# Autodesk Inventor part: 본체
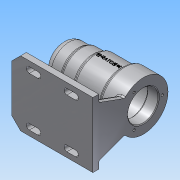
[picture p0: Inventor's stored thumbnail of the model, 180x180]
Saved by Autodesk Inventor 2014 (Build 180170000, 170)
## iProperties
Created: 2017-09
Part Number: 본체
Material: 알루미늄 6061
Document SubType Name: Modeling
Designer: NET
Density: 2.71 g/cm^3
Appearance: 알루미늄 - 평지
Mass: 699.003 g
Surface Area: 709.206 cm^2
Volume: 257.935 cm^3
Author: NET
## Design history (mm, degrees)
sketch "스케치1"
  geometry: L1 (0, 0)-(112, 0); L2 (0, 0)-(0, 25); L3 (0, 25)-(25, 25); L4 (25, 25)-(25, 27); L5 (25, 27)-(45, 27); L6 (45, 27)-(45, 30); L7 (45, 30)-(84, 30); L8 (84, 30)-(84, 34); L9 (84, 34)-(112, 34); L10 (112, 34)-(112, 0)
  constraints: 20 end point, 6 parallel, 3 perpendicular, 1 horizontal
  dimensions: "d0" = 50 diameter of L3 L1; "d1" = 54 diameter of L5 L1; "d2" = 60 diameter of L7 L1; "d3" = 68 diameter of L9 L1; "d4" = 25 distance of L2.end L3.end; "d5" = 45 distance from line of L2 L6.end; "d6" = 84 distance between parallel lines of L2 L8; "d7" = 112 distance from line of L2 L9.end
revolve "회전1" sketch "스케치1" stored, may be unused: angle "d8" = 90 deg
fillet "모깎기1" dims "d9" = 9
fillet "모깎기2" dims "d10" = 3
sketch "스케치2"
  geometry: L1 (81, -30)-(47.196, -30) reference; L2 (42, -27)-(26.644, -27) reference; L3 (22.172, -25)-(9, -25) reference; L4 (0, -16)-(0, 16) reference; L5 (9, 25)-(22.172, 25) reference; L6 (26.644, 27)-(42, 27) reference; L7 (47.196, 30)-(81, 30) reference; L8 (86.657, 34)-(112, 34) reference; L9 (112, 34)-(112, -34) reference; L10 (112, -34)-(86.657, -34) reference; L11 (6, 0)-(112, 0); L12 (112, -34)-(112, 34) reference; L13 (6, 0)-(6, 10.5); L14 (6, 10.5)-(9, 10.5); L15 (9, 10.5)-(9, 16); L16 (9, 16)-(13, 16); L17 (13, 16)-(13, 17.5); L18 (13, 17.5)-(31, 17.5); L19 (31, 17.5)-(31, 21); L20 (31, 21)-(43, 21); L21 (43, 21)-(43, 24); L22 (43, 24)-(97, 24); L23 (97, 24)-(97, 21); L24 (97, 21)-(112, 21); L25 (112, 21)-(112, 0); A1 r 3 centre (86.657, -31) between (83.828, -32) and (86.657, -34) reference; A2 r 3 centre (81, -33) between (83.828, -32) and (81, -30) reference; A3 r 3 centre (47.196, -27) between (44.598, -28.5) and (47.196, -30) reference; A4 r 3 centre (42, -30) between (44.598, -28.5) and (42, -27) reference; A5 r 3 centre (26.644, -24) between (24.408, -26) and (26.644, -27) reference; A6 r 3 centre (22.172, -28) between (24.408, -26) and (22.172, -25) reference; A7 r 9 centre (9, -16) between (0, -16) and (9, -25) reference; A8 r 9 centre (9, 16) between (9, 25) and (0, 16) reference; A9 r 3 centre (22.172, 28) between (22.172, 25) and (24.408, 26) reference; A10 r 3 centre (26.644, 24) between (26.644, 27) and (24.408, 26) reference; A11 r 3 centre (42, 30) between (42, 27) and (44.598, 28.5) reference; A12 r 3 centre (47.196, 27) between (47.196, 30) and (44.598, 28.5) reference; A13 r 3 centre (81, 33) between (81, 30) and (83.828, 32) reference; A14 r 3 centre (86.657, 31) between (86.657, 34) and (83.828, 32) reference; 1 further point
  constraints: 28 end point, 6 parallel, 6 perpendicular, 1 midpoint, 1 point on line, 1 vertical
  dimensions: "d11" = 3 distance of L13.end L14.end; "d12" = 4 distance of L15.end L16.end; "d13" = 18 distance of L17.end L18.end; "d14" = 12 distance of L19.end L20.end; "d15" = 54 distance of L21.end L22.end; "d16" = 15 distance of L23.end L24.end; "d17" = 21 diameter of L14 L11; "d18" = 32 diameter of L16 L11; "d19" = 35 diameter of L18 L11; "d20" = 42 diameter of L20 L11; "d21" = 48 diameter of L22 L11; "d22" = 42 diameter of L24 L11
revolve "회전2" sketch "스케치2" stored, may be unused: angle "d23" = 90 deg
chamfer "모따기1" distance "d24" = 1; stored, may be unused: second distance "d25" = 2, angle "d26" = 45 deg
fillet "모깎기3" dims "d27" = 3
fillet "모깎기4" dims "d28" = 0.3
fillet "모깎기5" dims "d29" = 3
sketch "스케치3" dims "d30" = 52
  geometry: C1 r 34 at (0, 0) reference; C2 r 22 at (0, 0) reference; 2 further points
  constraints: 2 vertical alignment, 1 coincident, 2 other
hole "구멍1" sketch "스케치3" at (0, 26) diameter "d31" = 3.242; stored, may be unused: countersink angle "d35" = 90 deg, drill point angle "d37" = 118 deg; dims "d32" = 8, "d33" = 4, "d34" = 2, "d36" = 11
node "작업 평면1"
sketch "스케치4"
  geometry: L1 (0, 16)-(0, -16) reference; L2 (-112, 34)-(-112, -34) reference; L3 (-86.657, 34)-(-112, 34) reference; L4 (-86.657, -34)-(-112, -34) reference; L5 (-112, 0)-(0, 0); L6 (-112, 45)-(0, 45); L7 (0, 45)-(0, -45); L8 (0, -45)-(-112, -45); L9 (-112, -45)-(-112, 45); L10 (-112, 45)-(0, -45); L11 (0, 45)-(-112, -45); 3 further points
  constraints: 14 end point, 5 midpoint, 3 parallel, 1 coincident, 1 horizontal, 1 horizontal alignment, 1 perpendicular
  dimensions: "d43" = 90 distance of L8.end L6.start; "d44" = 112 distance of L6.start L6.end
extrude "돌출1" join sketch "스케치4" distance "d45" = 8; taper "d46" = 0 deg
sketch "스케치5" dims "d43" = 90
  geometry: L1 (0, -45)-(112, -45) reference; L2 (0, 45)-(0, -45) reference; L3 (24, 34)-(36, 34); L4 (24, 30)-(36, 30); L5 (36, 38)-(24, 38); L6 (76, 34)-(88, 34); L7 (76, 30)-(88, 30); L8 (88, 38)-(76, 38); A1 r 4 centre (24, 34) between (24, 38) and (24, 30); A2 r 4 centre (36, 34) between (36, 30) and (36, 38); A3 r 4 centre (76, 34) between (76, 38) and (76, 30); A4 r 4 centre (88, 34) between (88, 30) and (88, 38); 3 further points
  constraints: 16 end point, 8 point on circle, 8 tangent, 4 centre point, 4 parallel, 2 midpoint, 1 horizontal alignment
  dimensions: "d47" = 34 vertical distance of point (0, 0) L3.start; "d48" = 4 radius of A1; "d49" = 12 distance of L3.start L3.end; "d50" = 40 distance of L6.start L3.end; "d51" = 24 distance from line of L2 L3.start; "d52" = 12 distance of L6.start L6.end; "d53" = 4 radius of A3
extrude "돌출2" cut sketch "스케치5" distance "d54" = 8; taper "d55" = 0 deg
chamfer "모따기2" distance "d56" = 12; stored, may be unused: second distance "d57" = 2, angle "d58" = 45 deg
sketch "스케치6"
  geometry: L1 (-45, -62)-(45, -62) reference; L2 (-63, -70)-(63, -70) reference; L3 (-45, -70)-(-45, -62) reference; L4 (45, -70)-(45, -62) reference; L5 (35, -62)-(21.9, -26.008); L6 (-35, -62)-(-21.9, -26.008); L7 (-35, -62)-(35, -62); L8 (30, -62)-(38, -62) reference; A1 r 34 centre (0, 0) between (21.9, -26.008) and (-21.9, -26.008) reference; 1 further point
  constraints: 6 end point, 2 point on circle, 2 point on line, 1 collinear, 2 other
  dimensions: "d59" = 10 distance from line of L3 L6.start; "d60" = 10 distance from line of L4 L5.start; "d61" = 70 deg angle of L1 L6; "d62" = 70 deg angle of L1 L5
extrude "돌출3" join sketch "스케치6" distance "d63" = 8; taper "d64" = 0 deg
sketch "스케치7"
  geometry: L1 (112, 22)-(111, 21) reference; L2 (111, 21)-(97, 21) reference; L3 (94, 24)-(46, 24) reference; L4 (43, 21)-(31.3, 21) reference; L5 (31, 20.7)-(31, 17.5) reference; L6 (31, 17.5)-(13.3, 17.5) reference; L7 (13, 17.2)-(13, 16) reference; L8 (13, 16)-(9.3, 16) reference; L9 (9, 15.7)-(9, 10.5) reference; L10 (6, 7.5)-(6, -7.5) reference; L11 (9, -10.5)-(9, -15.7) reference; L12 (9.3, -16)-(13, -16) reference; L13 (13, -16)-(13, -17.2) reference; L14 (13.3, -17.5)-(31, -17.5) reference; L15 (31, -17.5)-(31, -20.7) reference; L16 (31.3, -21)-(43, -21) reference; L17 (46, -24)-(94, -24) reference; L18 (97, -21)-(111, -21) reference; L19 (111, -21)-(112, -22) reference; L20 (112, -22)-(112, -70) reference; L21 (112, -70)-(0, -70) reference; L22 (0, -70)-(0, -62) reference; L23 (0, -62)-(104, -62) reference; L24 (104, -62)-(104, -34) reference; L25 (104, -34)-(86.657, -34) reference; L26 (81, -30)-(47.196, -30) reference; L27 (42, -27)-(26.644, -27) reference; L28 (22.172, -25)-(9, -25) reference; L29 (0, -16)-(0, 16) reference; L30 (9, 25)-(22.172, 25) reference; L31 (26.644, 27)-(42, 27) reference; L32 (47.196, 30)-(81, 30) reference; L33 (86.657, 34)-(112, 34) reference; L34 (112, 34)-(112, 27.621) reference; L35 (112, 27.621)-(101, 27.621) reference; L36 (101, 27.621)-(100.026, 26) reference; L37 (100.026, 26)-(101, 24.379) reference; L38 (101, 24.379)-(112, 24.379) reference; L39 (112, 24.379)-(112, 22) reference; L40 (112, -62)-(12, -62) reference; L41 (22, -62)-(31.378, -27); L42 (22, -62)-(104, -62); L43 (104, -62)-(112, -62) reference; L44 (104, -62)-(104, -59.048); L45 (31.378, -27)-(33.181, -24); L46 (33.181, -24)-(53.836, -28); L47 (53.836, -28)-(73.946, -28); L48 (73.946, -28)-(94, -28.5); L49 (94, -28.5)-(104, -30.437); L50 (104, -26.008)-(104, -62) reference; L51 (104, -30.437)-(104, -34); A1 r 3 centre (94, 21) between (97, 21) and (94, 24) reference; A2 r 3 centre (46, 21) between (46, 24) and (43, 21) reference; A3 r 0.3 centre (31.3, 20.7) between (31.3, 21) and (31, 20.7) reference; A4 r 0.3 centre (13.3, 17.2) between (13.3, 17.5) and (13, 17.2) reference; A5 r 0.3 centre (9.3, 15.7) between (9.3, 16) and (9, 15.7) reference; A6 r 3 centre (9, 7.5) between (9, 10.5) and (6, 7.5) reference; A7 r 3 centre (9, -7.5) between (6, -7.5) and (9, -10.5) reference; A8 r 0.3 centre (9.3, -15.7) between (9, -15.7) and (9.3, -16) reference; A9 r 0.3 centre (13.3, -17.2) between (13, -17.2) and (13.3, -17.5) reference; A10 r 0.3 centre (31.3, -20.7) between (31, -20.7) and (31.3, -21) reference; A11 r 3 centre (46, -21) between (43, -21) and (46, -24) reference; A12 r 3 centre (94, -21) between (94, -24) and (97, -21) reference; A13 r 3 centre (86.657, -31) between (83.828, -32) and (86.657, -34) reference; A14 r 3 centre (81, -33) between (83.828, -32) and (81, -30) reference; A15 r 3 centre (47.196, -27) between (44.598, -28.5) and (47.196, -30) reference; A16 r 3 centre (42, -30) between (44.598, -28.5) and (42, -27) reference; A17 r 3 centre (26.644, -24) between (24.408, -26) and (26.644, -27) reference; A18 r 3 centre (22.172, -28) between (24.408, -26) and (22.172, -25) reference; A19 r 9 centre (9, -16) between (0, -16) and (9, -25) reference; A20 r 9 centre (9, 16) between (9, 25) and (0, 16) reference; A21 r 3 centre (22.172, 28) between (22.172, 25) and (24.408, 26) reference; A22 r 3 centre (26.644, 24) between (26.644, 27) and (24.408, 26) reference; A23 r 3 centre (42, 30) between (42, 27) and (44.598, 28.5) reference; A24 r 3 centre (47.196, 27) between (47.196, 30) and (44.598, 28.5) reference; A25 r 3 centre (81, 33) between (81, 30) and (83.828, 32) reference; A26 r 3 centre (86.657, 31) between (86.657, 34) and (83.828, 32) reference; 1 further point
  constraints: 18 end point, 4 point on line, 2 collinear, 2 parallel, 1 perpendicular
  dimensions: "d65" = 105 deg angle of L23 L41; "d66" = 22 distance from line of L22 L41.start
extrude "돌출4" join sketch "스케치7" stored distance "d67" = 8; taper "d68" = 0 deg
node "작업 평면2"
sketch "스케치8"
  geometry: 5 further points; 1 other entity
  constraints: 1 horizontal alignment, 2 other
  dimensions: "d72" = 48 dimension on point (64, 0)
feature "엠보싱1" sketch "스케치8" dims "d0" = 50, "d1" = 54, "d2" = 60, "d3" = 68, "d4" = 25, "d5" = 45, "d6" = 84, "d7" = 112, "d73" = 0.5, "d74" = 0
fillet "모깎기8" dims "d75" = 3
fillet "모깎기9" dims "d76" = 3
node "솔리드1"
pattern_circular "원형 패턴1" dims angle "d39" = 360 deg
mirror "대칭1"
node "절단 모서리 투영1"
node "절단 모서리 투영2"
